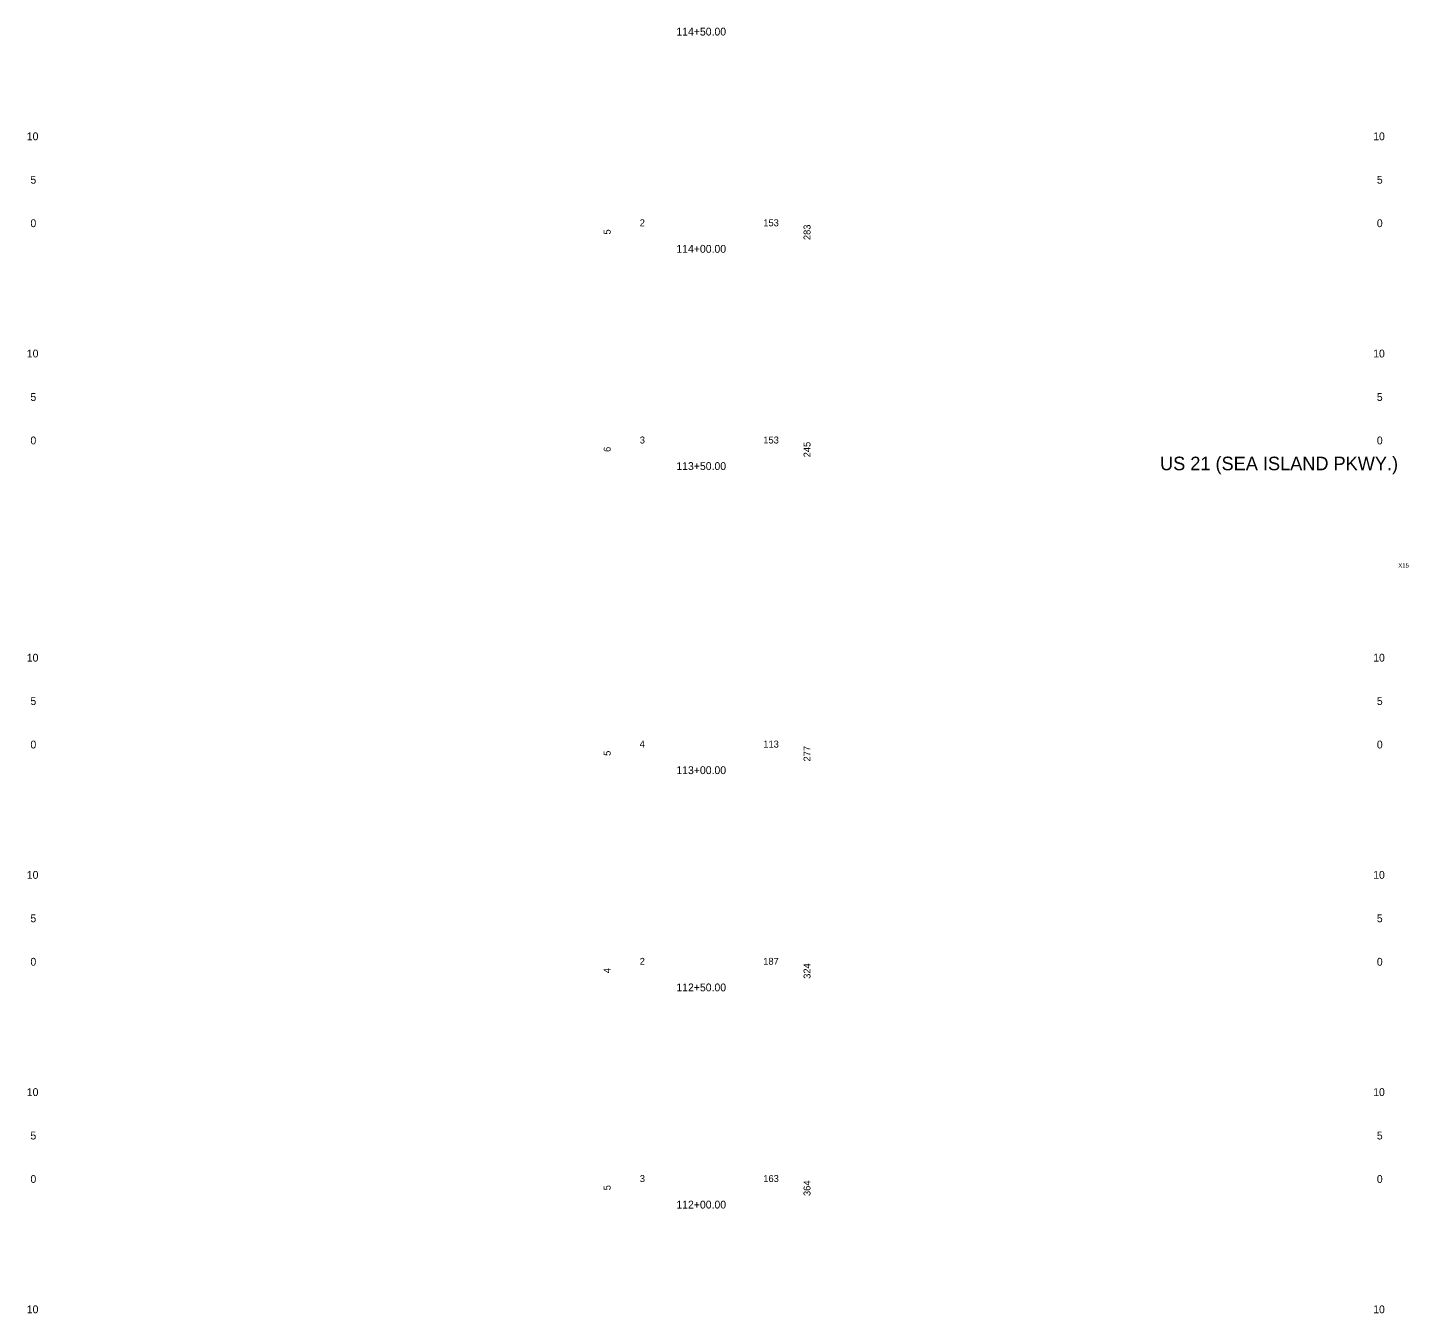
# Model space of a CAD drawing. Extents: x 971 to 1131, y 2203 to 6043.
# Drawn here: x 971.5 to 1130.5, y 5296.9 to 5444.8 of the extents above; entities that cross this region are included whole.
import ezdxf

# ---------------------------------------------------------------- set-up
doc = ezdxf.new("R2010")
doc.units = 0
for name, color, linetype in [('RD_SHT_Misc1', 7, 'Continuous'), ('RD_SHT_TX', 7, 'Continuous'), ('RD_XS_TX_Station', 7, 'Continuous')]:
    doc.layers.add(name, color=color, linetype=linetype)

msp = doc.modelspace()

# ---------------------------------------------------------------- texts
at = {"layer": 'RD_SHT_Misc1'}
for s, p in [('2', (1041.98, 5421.97)), ('153', (1056.21, 5421.97)), ('3', (1041.99, 5396.97)), ('153', (1056.21, 5396.97)), ('4', (1041.97, 5361.97)), ('113', (1056.21, 5361.97)), ('2', (1041.98, 5336.97)), ('187', (1056.2, 5336.97)), ('3', (1041.99, 5311.97)), ('163', (1056.21, 5311.97))]:
    msp.add_text(s, height=0.8, dxfattribs=at).set_placement(p)
for s, p in [('283', (1061.64, 5420.38)), ('5', (1038.63, 5421.02)), ('245', (1061.64, 5395.38)), ('6', (1038.63, 5396)), ('277', (1061.64, 5360.37)), ('5', (1038.63, 5361.02)), ('4', (1038.63, 5336)), ('324', (1061.64, 5335.36)), ('5', (1038.63, 5311.02)), ('364', (1061.64, 5310.36))]:
    msp.add_text(s, height=0.8, rotation=90, dxfattribs=at).set_placement(p)
at = {"layer": 'RD_SHT_TX'}
for s, height, p in [('10', 0.9, (971.42, 5431.87)), ('10', 0.9, (1126.42, 5431.87)), ('5', 0.9, (971.84, 5426.87)), ('5', 0.9, (1126.84, 5426.87)), ('0', 0.9, (971.84, 5421.87)), ('0', 0.9, (1126.84, 5421.87)), ('10', 0.9, (971.42, 5406.87)), ('10', 0.9, (1126.42, 5406.87)), ('5', 0.9, (971.84, 5401.87)), ('5', 0.9, (1126.84, 5401.87)), ('0', 0.9, (971.84, 5396.87)), ('0', 0.9, (1126.84, 5396.87)), ('US 21 (SEA ISLAND PKWY.)', 1.5625, (1101.88, 5393.89)), ('10', 0.9, (971.42, 5371.87)), ('10', 0.9, (1126.42, 5371.87)), ('5', 0.9, (971.84, 5366.87)), ('5', 0.9, (1126.84, 5366.87)), ('0', 0.9, (971.84, 5361.87)), ('0', 0.9, (1126.84, 5361.87)), ('10', 0.9, (971.42, 5346.87)), ('10', 0.9, (1126.42, 5346.87)), ('5', 0.9, (971.84, 5341.87)), ('5', 0.9, (1126.84, 5341.87)), ('0', 0.9, (971.84, 5336.87)), ('0', 0.9, (1126.84, 5336.87)), ('10', 0.9, (971.42, 5321.87)), ('10', 0.9, (1126.42, 5321.87)), ('5', 0.9, (971.84, 5316.87)), ('5', 0.9, (1126.84, 5316.87)), ('0', 0.9, (971.84, 5311.87)), ('0', 0.9, (1126.84, 5311.87)), ('10', 0.9, (971.42, 5296.87)), ('10', 0.9, (1126.42, 5296.87))]:
    msp.add_text(s, height=height, dxfattribs=at).set_placement(p)
msp.add_text('X15', height=0.5, rotation=360, dxfattribs=at).set_placement((1129.31, 5382.68))
at = {"layer": 'RD_XS_TX_Station'}
for s, p in [('114+50.00', (1046.2, 5443.92)), ('114+00.00', (1046.2, 5418.92)), ('113+50.00', (1046.2, 5393.92)), ('113+00.00', (1046.2, 5358.92)), ('112+50.00', (1046.2, 5333.92)), ('112+00.00', (1046.2, 5308.92))]:
    msp.add_text(s, height=0.9, dxfattribs=at).set_placement(p)

doc.saveas('drawing.dxf')
